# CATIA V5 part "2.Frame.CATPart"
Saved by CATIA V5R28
Part number: Frame
Bounding box of the stored display mesh (mm): x -70 to 70, y -361.531 to 366.584, z -27.5 to 283.589
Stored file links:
  D:\Catia Cycle design\2.Frame.CATPart
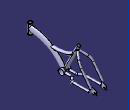
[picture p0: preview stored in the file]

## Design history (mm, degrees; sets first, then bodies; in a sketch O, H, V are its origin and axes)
Set1
  Plane1: type Normal, Curve Sketch1, RefPoint Sketch1.P2, Ratio 0
  Plane2: type Normal, Curve Sketch1, RefPoint Sketch1.O, Ratio 0
  Extremum1: Reference Sketch2, Direction (1, 2, 3)
  Extremum2: Reference Sketch3, Direction (1, 2, 3)
  Plane3: type Normal, Curve Sketch4, RefPoint Sketch4.P1, Ratio 0
  Circle1: type CtrRad, Start 0, End 180, Center Sketch4.P1, Support Plane3, Radius 17.5, FirstDirection (1, 0, 0)
  Plane4: type Offset, RefPlane zx-plane, Offset 10
  Point1: type Center, Curve Sketch7
  Point2: (60, 125, -7.5), relative to Sketch7.O
  Line1: type PtDir, RefPoint Point1, Direction zx-plane, Start 0, End 85
  Line2: type PtDir, RefPoint Point2, Direction zx-plane, Start 0, End 207.45
  Plane5: type OffsetPt, RefPlane yz-plane, RefPoint vertex of Line2
  Line3: type PtPt, FirstPoint vertex of Line1, SecondPoint Point2
  Line4: type PtPt, FirstPoint Sketch6.P2, SecondPoint Sketch8.P3
  Corner1: Element1 Line1, Element2 Line3, Radius 15
  Corner2: Element1 Corner1, Element2 Line2, Radius 30
  Corner3: Element1 Corner2, Element2 Sketch6, Radius 20
  Corner4: Element1 Corner3, Element2 Line4, Radius 100
  Plane6: type Normal, Curve Sketch8, RefPoint Sketch8.P4, Ratio 0
  Circle2: type CtrRad, Start 0, End 180, Center Sketch8.P4, Support Plane6, Radius 15, FirstDirection (1, 0, 0)
  Plane7: type Normal, Curve Sketch9, RefPoint Sketch9.P2, Ratio 0
  Circle3: type CtrRad, Start 0, End 180, Center Sketch9.P2, Support Plane7, Radius 15, FirstDirection (-1, 0, 0)
  Plane8: type Offset, RefPlane yz-plane, Offset 46
Body1 (main body)
  Sketch1 on yz-plane, origin (0, 0, 0), H (0, 1, 0), V (0, 0, 1)
    arc A1 centre (-341.5305, -215.5768) radius 403.8768 from (0, 0) to (-341.5305, 188.3) ccw
    point P2 (-341.5305, 188.3)
    axis line L1 (-341.5305, 188.3) -> (91.4538, 188.3)
    distance O P2 = 390
    distance P2 H = 188.3
    tangency: A1 L1
    horizontal: L1 H
  Sketch2 on Plane1, origin (0, -341.5305, 0), H (1, 0, 0), V (0, 0, 1)
    point P1 (0, 188.3)
    ellipse A1 centre (0, 188.3) semi-axes 32.5, 17.5 rotation 90
    point P2 (0, 220.8)
    reference projected point E1 (0, 188.3) from Sketch1.P2
    "Radius" A1 = 32.5
    distance P1 A1 = 17.5
    coincidence: P1 V, P2 V, A1 P2, P1 E1
    vertical: A1 V
  Sketch3 on Plane2, origin (0, 0, 0), H (1, 0, 0), V (0, 0.8456, 0.5338)
    point P1 (0, 0)
    ellipse A1 centre (0, 0) semi-axes 27.5, 17.5 rotation 90
    point P2 (0, 27.5)
    "Radius" A1 = 27.5
    distance P1 A1 = 17.5
    coincidence: P1 V, P2 V, A1 P2, P1 O
    vertical: A1 V
  Loft1: solid, Sections (Sketch2; Sketch3), Spine Sketch1
  Sketch4 on yz-plane, origin (0, 0, 0), H (0, 1, 0), V (0, 0, 1)
    line L1 (-341.5305, 232.7888) -> (-341.5305, 187.7888)
    point P1 (-341.5305, 232.7888)
    point P2 (-341.5305, 187.7888)
    reference projected point E1 (-341.5305, 220.2888) from Extremum1
    reference projected line E2 (-341.5305, 155.8) -> (-341.5305, 220.8) from edge [face of Loft1 | face of Loft1]
    length L1 = 45
    distance E1 P2 V = 32.5
    vertical: L1 V
    coincidence: L1 E2
  Pad1: profile Circle1, length 90
  Sketch5 on yz-plane, origin (0, 0, 0), H (0, 1, 0), V (0, 0, 1)
    circle A1 centre (0, 0) radius 27.5
    radius A1 = 27.5
  Pad2: profile Sketch5, direction (1, 0, 0), length 37.5, mirrored extent
  Sketch6 on Plane5, origin (60, 0, 0), H (0, 1, 0), V (0, 0, 1)
    line L1 (342.45, -7.5) -> (205.6, 177.3569)
    point P1 (342.45, -7.5)
    point P2 (205.6, 177.3569)
    reference projected point E1 (342.45, -7.5) from vertex of Line2
    reference projected line E2 (300, 0) -> (121.5, 241.1177) from Sketch8.L2
    length L1 = 230
    coincidence: P1 E1
    parallelism: E2 L1
  Sketch7 on Plane4, origin (0, 10, 0), H (-1, 0, 0), V (0, 0, 1)
    circle A1 centre (-22.5, 0) radius 10
    point P1 (-22.5, 0)
    reference projected line E1 (-37.5, -27.5) -> (-37.5, 27.5) from edge [face of Pad2 from Sketch5.A1 | end face of Pad2]
    radius A1 = 10
    distance E1 P1 = 15
    coincidence: P1 H
  Sketch8 on yz-plane, origin (0, 0, 0), H (0, 1, 0), V (0, 0, 1)
    point P1 (0, 0)
    line L1 (0, 0) -> (300, 0)
    line L2 (300, 0) -> (121.5, 241.1177)
    point P3 (121.5, 241.1177)
    line L3 (0, 0) -> (139.5, 276.8389)
    point P4 (139.5, 276.8389)
    length L2 = 300
    length L1 = 300
    distance P3 P1 = 270
    distance P4 P3 = 40
    coincidence: P1 H, L3 P3, P1 O
    horizontal: L1 H
  Rib1: profile Sketch7, centre curve Corner4
  Mirror1: of Rib1, about yz-plane
  Pad3: profile Circle2, up to the existing solid (limit type 2)
  Fillet1: radius 5, on edge [face of Rib1 | face of Pad3]; edge [face of Pad3 | face of Mirror1]; edge [face of Pad2 from Sketch5.A1 | face of Rib1]; edge [face of Pad2 from Sketch5.A1 | face of Pad3]; edge [face of Mirror1 | face of Pad2 from Sketch5.A1]
  Sketch9 on yz-plane, origin (0, 0, 0), H (0, 1, 0), V (0, 0, 1)
    arc A1 centre (-78.6577, 456.9459) radius 320 from (-150, 145) to (90, 185) ccw
    point P2 (-150, 145)
    point P3 (90, 185)
    distance P3 H = 185
    radius A1 = 320
    distance P3 V = 90
    distance P2 H = 145
    distance P2 V = 150
  Rib2: profile Circle3, centre curve Sketch9
  Sketch10 on end face of Pad2, origin (37.5, 0, 0), H (0, 1, 0), V (0, 0, 1)
    offset circle E1 centre (0, 0) radius 26 from edge [face of Pad2 from Sketch5.A1 | end face of Pad2]
  Pocket1: profile Sketch10, direction (-1, 0, 0), through (limit type 6)
  Sketch11 on start face of Pad3, origin (0, 139.5, 276.8389), H (-1, 0, 0), V (0, -0.893, 0.45)
    offset circle E1 centre (0, 0) radius 13.5 from edge [face of Pad3 | start face of Pad3]
  Pocket2: profile Sketch11, direction (0, -0.45, -0.893), through (limit type 6)
  Sketch12 on start face of Pad1, origin (0, 0, 232.7888), H (1, 0, 0), V (0, 1, 0)
    offset circle E1 centre (0, -341.5305) radius 16 from start face of Pad1
  Pocket3: profile Sketch12, direction (0, 0, -1), through (limit type 6)
  Sketch13 on start face of Pad1, origin (0, 0, 232.7888), H (1, 0, 0), V (0, 1, 0)
    circle A1 centre (0, -341.5305) radius 20
    point P1 (0, -341.5305)
    reference projected circle E1 centre (0, -341.5305) radius 17.5 from edge [face of Pad1 | start face of Pad1]
    projected circle E2 centre (0, -341.5305) radius 16 from edge [start face of Pad1 | face of Pocket3 from Sketch12.E1]
    radius A1 = 20
    coincidence: P1 V
    concentricity: A1 E1
  Pad4: profile Sketch13, direction (0, 0, 1), length 5
  Pad5: profile Sketch13, direction (0, 0, -1), length 95, opposite side length -90
  Sketch14 on Plane8, origin (46, 0, 0), H (0, 1, 0), V (0, 0, 1)
    reference projected line E2 (326.8716, 30.35) -> (231.52, 159.1509) from face of Rib1
    reference projected line E3 (147.0336, -17.5) -> (302.7598, -17.5) from face of Rib1
    point P6 (302.7598, -17.5)
    point P9 (366.5837, -16.66)
    line L1 (366.5837, -12.66) -> (366.5837, -10.66)
    point P10 (366.5837, -6.66)
    line L2 (362.5837, -6.66) -> (343.6837, -6.66)
    arc A1 centre (343.6837, -1.66) radius 5 from (343.6837, -6.66) to (343.6837, 3.34) cw
    line L3 (343.6837, 3.34) -> (362.5837, 3.34)
    point P14 (366.5837, 3.34)
    line L4 (366.5837, 7.34) -> (366.5837, 15.2182)
    line L5 (364.2742, 18.8434) -> (326.0677, 36.6593)
    point P15 (320.1621, 39.4132)
    line L6 (319.0306, 32.996) -> (311.3096, -10.7918)
    point P16 (310.2749, -16.66)
    line L7 (316.2337, -16.66) -> (362.5837, -16.66)
    point P17 (310.2749, -16.66)
    arc A2 centre (316.2337, -11.66) radius 5 from (311.3096, -10.7918) to (316.2337, -16.66) ccw
    point P19 (316.2337, -16.66)
    arc A3 centre (323.9547, 32.1278) radius 5 from (326.0677, 36.6593) to (319.0306, 32.996) ccw
    arc A4 centre (362.5837, 15.2182) radius 4 from (366.5837, 15.2182) to (364.2742, 18.8434) ccw
    arc A5 centre (362.5837, 7.34) radius 4 from (362.5837, 3.34) to (366.5837, 7.34) ccw
    arc A6 centre (362.5837, -10.66) radius 4 from (366.5837, -10.66) to (362.5837, -6.66) ccw
    arc A7 centre (362.5837, -12.66) radius 4 from (366.5837, -12.66) to (362.5837, -16.66) cw
    distance L7 E3 = 0.84
    radius A1 = 5
    angle L6 L5 = 75
    angle L6 L7 = 80
    radius A2 = 5
    radius A3 = 5
    radius A4 = 4
    radius A5 = 4
    distance P9 P10 = 10
    radius A6 = 4
    radius A7 = 4
    length L7 = 46.35
    length L3 = 18.9
    distance P6 P19 = 13.5
    vertical: L1 V, L4 V
    horizontal: L2 H, L7 H, L3 H
    tangency: A1 L2, L3 A1, A2 L6, A2 L7, A3 L5, A3 L6, A4 L4, A4 L5, A5 L3, A5 L4, A6 L1, A6 L2, A7 L1, A7 L7
    coincidence: P14 L1, P15 E2, P17 P16, L6 P16, L7 P17, L5 P15, L6 P15, L3 P14, L4 P14, L1 P10, L2 P10, L1 P9, L7 P9
  Pad6: profile Sketch14, direction (1, 0, 0), length 4
  Mirror2: of Pad6, about yz-plane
